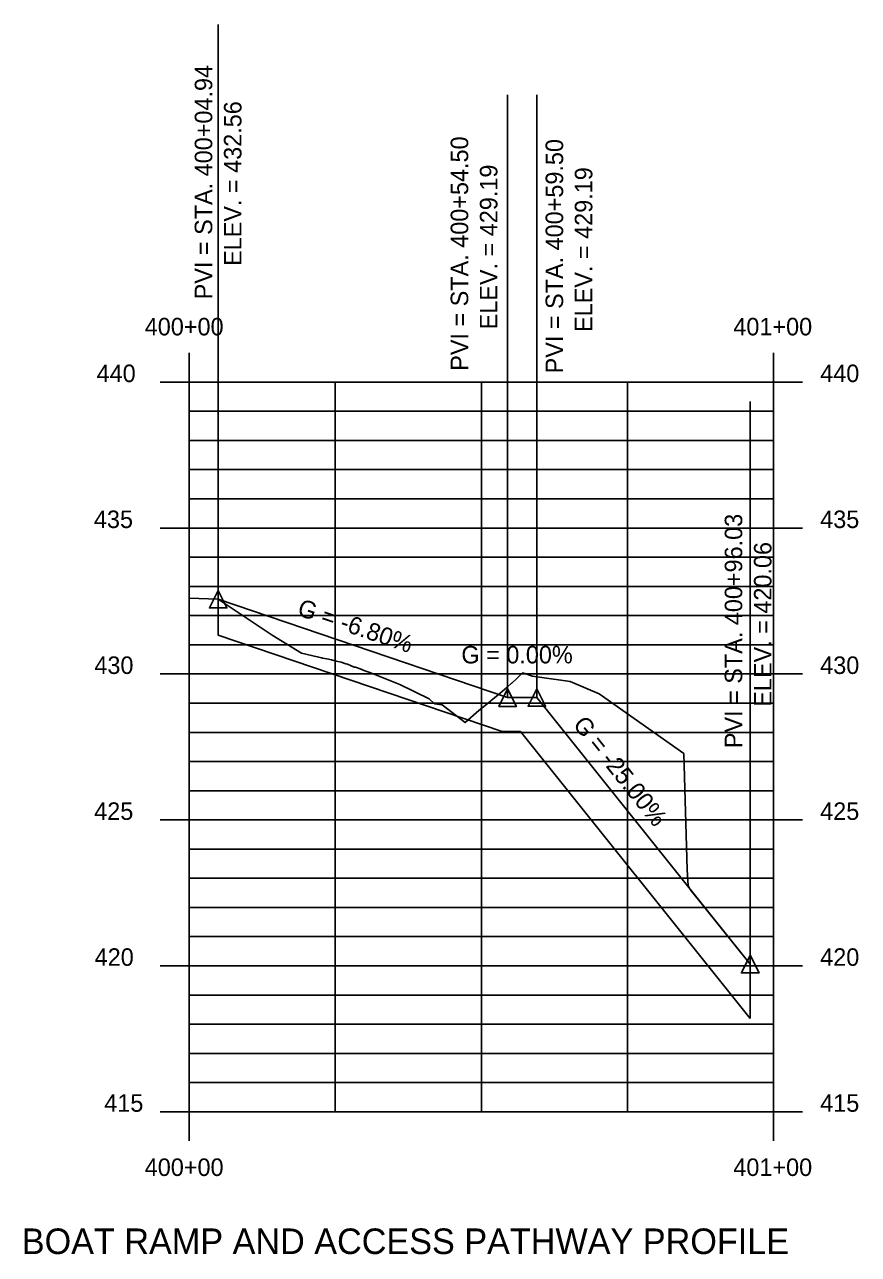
# Model space of a CAD drawing. Extents: x 939096 to 939239, y 629780 to 629991.
import ezdxf

# ---------------------------------------------------------------- set-up
doc = ezdxf.new("R2010")
doc.units = 0
for name, color, linetype in [('ANNOTATION', 7, 'Continuous'), ('D_Roadway_Centerline', 7, 'Continuous'), ('D_Roadway_Centerline_CurveData', 7, 'Continuous'), ('H_V ANNOTATION', 7, 'Continuous'), ('MAJOR', 7, 'Continuous'), ('MINOR', 7, 'Continuous'), ('S_Roadway_Centerline', 7, 'Continuous')]:
    doc.layers.add(name, color=color, linetype=linetype)

msp = doc.modelspace()

# ---------------------------------------------------------------- linework, layer by layer
at = {"layer": 'D_Roadway_Centerline'}
for p, q in [((939129.22, 629892.09), (939178.78, 629875.23)), ((939129.22, 629892.09), (939129.22, 629885.93)), ((939129.22, 629885.93), (939177.82, 629869.4)), ((939178.78, 629875.23), (939183.79, 629875.24)), ((939183.79, 629875.24), (939220.31, 629829.58)), ((939177.82, 629869.4), (939180.98, 629869.4)), ((939180.98, 629869.4), (939220.31, 629820.25)), ((939220.31, 629829.58), (939220.31, 629820.25))]:
    msp.add_line(p, q, dxfattribs=at)
at = {"layer": 'D_Roadway_Centerline_CurveData'}
for p, q in [((939129.22, 629917.09), (939129.22, 629990.52)), ((939178.78, 629900.23), (939178.78, 629978.5)), ((939183.79, 629900.24), (939183.79, 629978.48)), ((939220.31, 629854.58), (939220.31, 629925.98)), ((939129.22, 629892.09), (939129.22, 629917.09)), ((939178.78, 629875.23), (939178.78, 629900.23)), ((939183.79, 629875.24), (939183.79, 629900.24)), ((939220.31, 629829.58), (939220.31, 629854.58))]:
    msp.add_line(p, q, dxfattribs=at)
for points in [[(939129.22, 629893.59), (939130.72, 629890.59), (939127.72, 629890.59)], [(939178.78, 629876.73), (939180.28, 629873.73), (939177.28, 629873.73)], [(939183.79, 629876.74), (939185.29, 629873.74), (939182.29, 629873.74)], [(939220.31, 629831.08), (939221.81, 629828.08), (939218.81, 629828.08)]]:
    msp.add_lwpolyline(points, close=True, dxfattribs=at)
at = {"layer": 'MAJOR'}
for p, q in [((939124.28, 629934.28), (939124.28, 629929.28)), ((939224.28, 629934.28), (939224.28, 629929.28)), ((939119.28, 629929.28), (939124.28, 629929.28)), ((939119.28, 629929.28), (939124.28, 629929.28)), ((939124.28, 629929.28), (939224.28, 629929.28)), ((939124.28, 629804.28), (939124.28, 629929.28)), ((939224.28, 629804.28), (939224.28, 629929.28)), ((939229.28, 629929.28), (939224.28, 629929.28)), ((939229.28, 629929.28), (939224.28, 629929.28)), ((939119.28, 629904.28), (939124.28, 629904.28)), ((939124.28, 629904.28), (939224.28, 629904.28)), ((939229.28, 629904.28), (939224.28, 629904.28)), ((939119.28, 629879.28), (939124.28, 629879.28)), ((939124.28, 629879.28), (939224.28, 629879.28)), ((939229.28, 629879.28), (939224.28, 629879.28)), ((939119.28, 629854.28), (939124.28, 629854.28)), ((939124.28, 629854.28), (939224.28, 629854.28)), ((939229.28, 629854.28), (939224.28, 629854.28)), ((939119.28, 629829.28), (939124.28, 629829.28)), ((939124.28, 629829.28), (939224.28, 629829.28)), ((939229.28, 629829.28), (939224.28, 629829.28)), ((939119.28, 629804.28), (939124.28, 629804.28)), ((939124.28, 629804.28), (939224.28, 629804.28)), ((939124.28, 629799.28), (939124.28, 629804.28)), ((939229.28, 629804.28), (939224.28, 629804.28)), ((939224.28, 629799.28), (939224.28, 629804.28))]:
    msp.add_line(p, q, dxfattribs=at)
at = {"layer": 'MINOR'}
for p, q in [((939149.28, 629804.28), (939149.28, 629929.28)), ((939174.28, 629804.28), (939174.28, 629929.28)), ((939199.28, 629804.28), (939199.28, 629929.28)), ((939124.28, 629924.28), (939224.28, 629924.28)), ((939124.28, 629919.28), (939224.28, 629919.28)), ((939124.28, 629914.28), (939224.28, 629914.28)), ((939124.28, 629909.28), (939224.28, 629909.28)), ((939124.28, 629899.28), (939224.28, 629899.28)), ((939124.28, 629894.28), (939224.28, 629894.28)), ((939124.28, 629889.28), (939224.28, 629889.28)), ((939124.28, 629884.28), (939224.28, 629884.28)), ((939124.28, 629874.28), (939224.28, 629874.28)), ((939124.28, 629869.28), (939224.28, 629869.28)), ((939124.28, 629864.28), (939224.28, 629864.28)), ((939124.28, 629859.28), (939224.28, 629859.28)), ((939124.28, 629849.28), (939224.28, 629849.28)), ((939124.28, 629844.28), (939224.28, 629844.28)), ((939124.28, 629839.28), (939224.28, 629839.28)), ((939124.28, 629834.28), (939224.28, 629834.28)), ((939124.28, 629824.28), (939224.28, 629824.28)), ((939124.28, 629819.28), (939224.28, 629819.28)), ((939124.28, 629814.28), (939224.28, 629814.28)), ((939124.28, 629809.28), (939224.28, 629809.28))]:
    msp.add_line(p, q, dxfattribs=at)
at = {"layer": 'S_Roadway_Centerline'}
msp.add_lwpolyline([(939124.28, 629892.26), (939129.22, 629892.09), (939138.47, 629885.93), (939143.47, 629882.87), (939146.18, 629882.23), (939147, 629882.03), (939147.09, 629882), (939147.82, 629881.86), (939148.63, 629881.69), (939149.45, 629881.5), (939149.7, 629881.44), (939150.27, 629881.28), (939151.09, 629881.03), (939151.39, 629880.93), (939151.9, 629880.72), (939152.5, 629880.47), (939152.72, 629880.43), (939152.93, 629880.39), (939153.54, 629880.16), (939154.35, 629879.84), (939155.17, 629879.52), (939158.88, 629878.05), (939160.34, 629877.49), (939165.37, 629875.02), (939166.27, 629874.16), (939167.6, 629873.98), (939171.51, 629870.94), (939173.84, 629873.04), (939175.5, 629874.36), (939176.3, 629875), (939177.09, 629875.66), (939177.89, 629876.33), (939178.68, 629877.02), (939179.43, 629877.68), (939179.48, 629877.73), (939180.28, 629878.47), (939181.07, 629879.23), (939181.32, 629879.47), (939181.87, 629879.28), (939182.67, 629879.03), (939183.02, 629878.91), (939183.46, 629878.85), (939184.26, 629878.73), (939189.46, 629878.01), (939194.42, 629875.86), (939208.93, 629865.65), (939209.51, 629845.71), (939209.7, 629843.06), (939210.02, 629842.34), (939220.3, 629829.59), (939220.31, 629829.58)], dxfattribs=at)

# ---------------------------------------------------------------- texts
at = {"layer": 'ANNOTATION'}
msp.add_text('BOAT RAMP AND ACCESS PATHWAY PROFILE', height=4.375, dxfattribs=at).set_placement((939095.62, 629779.91))
at = {"layer": 'D_Roadway_Centerline_CurveData'}
for s, rotation, p in [('PVI = STA. 400+04.94', 90, (939128.22, 629943.46)), ('ELEV. = 432.56', 90, (939133.22, 629949.18)), ('PVI = STA. 400+54.50', 90, (939172.03, 629931.22)), ('PVI = STA. 400+59.50', 90, (939188.28, 629930.77)), ('ELEV. = 429.19', 90, (939177.03, 629938.32)), ('ELEV. = 429.19', 90, (939193.28, 629937.87)), ('PVI = STA. 400+96.03', 90, (939218.94, 629866.57)), ('ELEV. = 420.06', 90, (939223.94, 629873.67)), ('G = -6.80%', 341.2183, (939142.6, 629889.4)), ('G = 0.00%', 0.0388, (939170.86, 629881.08)), ('G = -25.00%', 308.6621, (939189.82, 629870.55))]:
    msp.add_text(s, height=3, rotation=rotation, dxfattribs=at).set_placement(p)
at = {"layer": 'H_V ANNOTATION'}
for s, p in [('400+00', (939116.66, 629937.28)), ('401+00', (939217.41, 629937.28)), ('440', (939108.42, 629929.28)), ('440', (939108.42, 629929.28)), ('440', (939232.28, 629929.28)), ('440', (939232.28, 629929.28)), ('435', (939107.96, 629904.28)), ('435', (939232.28, 629904.28)), ('430', (939108.04, 629879.28)), ('430', (939232.28, 629879.28)), ('425', (939108.01, 629854.28)), ('425', (939232.28, 629854.28)), ('420', (939108.09, 629829.28)), ('420', (939232.28, 629829.28)), ('415', (939109.73, 629804.28)), ('415', (939232.28, 629804.28)), ('400+00', (939116.66, 629793.28)), ('401+00', (939217.41, 629793.28))]:
    msp.add_text(s, height=3, dxfattribs=at).set_placement(p)

doc.saveas('drawing.dxf')
